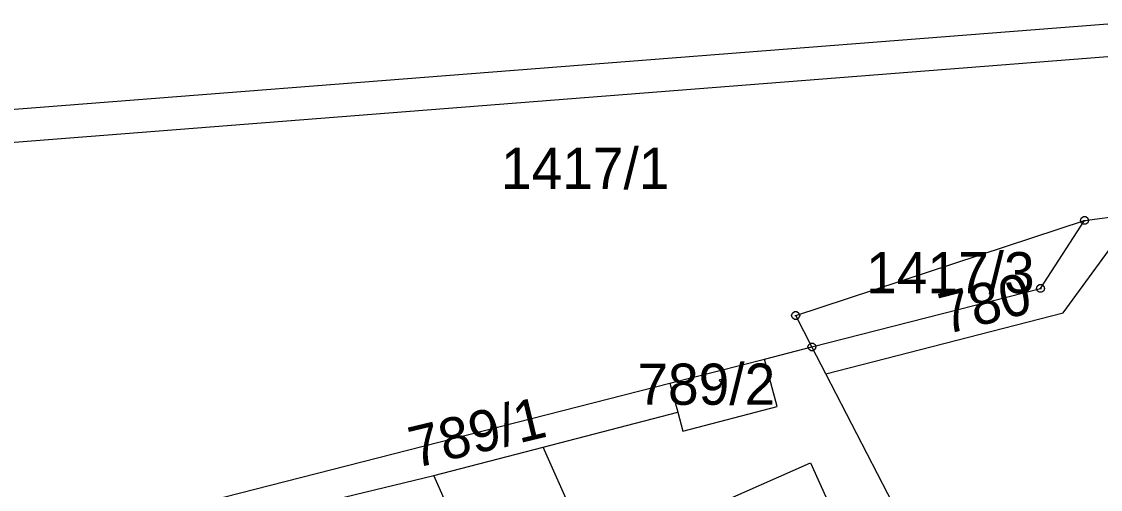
# Model space of a CAD drawing. Extents: x -510185 to -506993, y -1126306 to -1123642.
# Drawn here: x -508646.3 to -508512.8, y -1126171.4 to -1126113.4 of the extents above; entities that cross this region are included whole.
import ezdxf

# ---------------------------------------------------------------- set-up
doc = ezdxf.new("R2010")
doc.units = 0
for name, color, linetype in [('parcelni hranice', 7, 'Continuous'), ('u_dráha', 7, 'Continuous'), ('ˇ2', 7, 'Continuous'), ('ˇ4', 7, 'Continuous'), ('ˇ5', 7, 'Continuous'), ('ˇ8', 7, 'Continuous')]:
    doc.layers.add(name, color=color, linetype=linetype)

msp = doc.modelspace()

# ---------------------------------------------------------------- linework, layer by layer
at = {"layer": 'parcelni hranice'}
for p, q in [((-508514.77, -1126138.08), (-508491.86, -1126135.16)), ((-508550.52, -1126149.85), (-508514.77, -1126138.08)), ((-508520.22, -1126146.5), (-508514.77, -1126138.08)), ((-508517.41, -1126149.51), (-508511.34, -1126141.23)), ((-508548.51, -1126153.74), (-508520.22, -1126146.5)), ((-508548.51, -1126153.74), (-508550.52, -1126149.85)), ((-508546.79, -1126157.07), (-508517.41, -1126149.51)), ((-508554.4, -1126155.25), (-508548.51, -1126153.74)), ((-508546.79, -1126157.07), (-508548.51, -1126153.74)), ((-508566.08, -1126158.23), (-508554.4, -1126155.25)), ((-508552.8, -1126161.14), (-508554.4, -1126155.25)), ((-508533.68, -1126182.44), (-508546.79, -1126157.07)), ((-508625.06, -1126173.32), (-508566.08, -1126158.23)), ((-508566.08, -1126158.23), (-508565.12, -1126161.83)), ((-508581.77, -1126166.15), (-508565.12, -1126161.83)), ((-508565.12, -1126161.83), (-508564.49, -1126164.19)), ((-508564.49, -1126164.19), (-508552.8, -1126161.14)), ((-508595.32, -1126169.66), (-508581.77, -1126166.15)), ((-508575.63, -1126179.97), (-508581.77, -1126166.15)), ((-508620.08, -1126175.63), (-508595.32, -1126169.66)), ((-508584, -1126195.2), (-508595.32, -1126169.66))]:
    msp.add_line(p, q, dxfattribs=at)
at = {"layer": 'u_dráha'}
for p, q in [((-508819.61, -1126137.77), (-508508.51, -1126113.45)), ((-508508.22, -1126117.52), (-508819.26, -1126141.91))]:
    msp.add_line(p, q, dxfattribs=at)
at = {"layer": 'ˇ4'}
for p, q in [((-508575.63, -1126179.97), (-508548.69, -1126168.11)), ((-508548.69, -1126168.11), (-508544.03, -1126178.44))]:
    msp.add_line(p, q, dxfattribs=at)
at = {"layer": 'ˇ5'}
msp.add_lwpolyline([(-508559.68, -1126157.77), (-508559.6, -1126157.92), (-508559.68, -1126158.07), (-508559.86, -1126158.07), (-508559.95, -1126157.92), (-508559.86, -1126157.77)], close=True, dxfattribs=at)
at = {"layer": 'ˇ8'}
for points in [[(-508514.62, -1126137.6), (-508514.37, -1126137.79), (-508514.27, -1126138.08), (-508514.37, -1126138.37), (-508514.62, -1126138.56), (-508514.92, -1126138.56), (-508515.17, -1126138.37), (-508515.27, -1126138.08), (-508515.17, -1126137.79), (-508514.92, -1126137.6)], [(-508520.07, -1126146.02), (-508519.82, -1126146.21), (-508519.72, -1126146.5), (-508519.82, -1126146.79), (-508520.07, -1126146.98), (-508520.37, -1126146.98), (-508520.62, -1126146.79), (-508520.72, -1126146.5), (-508520.62, -1126146.21), (-508520.37, -1126146.02)], [(-508550.37, -1126149.37), (-508550.12, -1126149.56), (-508550.02, -1126149.85), (-508550.12, -1126150.14), (-508550.37, -1126150.33), (-508550.67, -1126150.33), (-508550.92, -1126150.14), (-508551.02, -1126149.85), (-508550.92, -1126149.56), (-508550.67, -1126149.37)], [(-508548.36, -1126153.26), (-508548.11, -1126153.45), (-508548.01, -1126153.74), (-508548.11, -1126154.03), (-508548.36, -1126154.22), (-508548.66, -1126154.22), (-508548.91, -1126154.03), (-508549.01, -1126153.74), (-508548.91, -1126153.45), (-508548.66, -1126153.26)]]:
    msp.add_lwpolyline(points, close=True, dxfattribs=at)
for points in [[(-508514.89, -1126138.08), (-508514.65, -1126138.08)], [(-508520.34, -1126146.5), (-508520.1, -1126146.5)], [(-508550.64, -1126149.85), (-508550.4, -1126149.85)], [(-508548.63, -1126153.74), (-508548.39, -1126153.74)]]:
    msp.add_lwpolyline(points, dxfattribs=at)

# ---------------------------------------------------------------- texts
at = {"layer": 'ˇ2'}
for s, p in [('1417/1', (-508587, -1126134.18)), ('1417/3', (-508541.81, -1126147.1)), ('789/2', (-508570.12, -1126160.91))]:
    msp.add_text(s, height=5.1, dxfattribs=at).set_placement(p)
for s, rotation, p in [('780', 14.3812, (-508531.99, -1126152.22)), ('789/1', 13.4645, (-508597.68, -1126168.78))]:
    msp.add_text(s, height=5.1, rotation=rotation, dxfattribs=at).set_placement(p)

doc.saveas('drawing.dxf')
